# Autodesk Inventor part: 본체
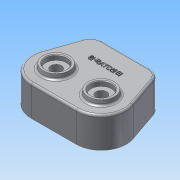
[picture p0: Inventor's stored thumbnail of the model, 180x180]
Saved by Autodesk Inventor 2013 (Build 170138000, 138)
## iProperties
Created: 2014-12
Part Number: 본체
Material: 알루미늄 6061
Document SubType Name: Modeling
Designer: Administrator
Density: 2.71 g/cm^3
Mass: 612.316 g
Surface Area: 666.735 cm^2
Volume: 225.947 cm^3
Author: Administrator
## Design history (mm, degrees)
sketch "스케치1"
  geometry: L1 (-47, 36)-(47, 36); L2 (47, 36)-(66.565, -20.803); L3 (32.527, -68.527)-(-32.527, -68.527); L4 (-66.565, -20.803)-(-47, 36); L5 (0, 0)-(-32.527, -32.527); L6 (0, 0)-(32.527, -32.527); A1 r 36 centre (-32.527, -32.527) between (-66.565, -20.803) and (-32.527, -68.527); A2 r 36 centre (32.527, -32.527) between (32.527, -68.527) and (66.565, -20.803); 2 further points
  constraints: 12 end point, 4 point on circle, 4 tangent, 2 centre point, 2 midpoint, 2 perpendicular, 2 vertical alignment, 1 horizontal, 1 parallel
  dimensions: "d0" = 94 distance of L1.start L1.end; "d89" = 72 diameter of A1; "d90" = 72 diameter of A2; "d91" = 36 distance from line of L1 L5.start; "d92" = 46 distance of L5.start L5.end
extrude "돌출1" new body sketch "스케치1" distance "d30" = 44; taper "d31" = 0 deg
fillet "모깎기2" dims "d33" = 18
sketch "스케치13"
  geometry: L1 (-34.162, 36)-(34.162, 36) reference; L2 (51.181, 23.862)-(66.565, -20.803) reference; L3 (-66.565, -20.803)-(-51.181, 23.862) reference; L4 (-34.162, 36)-(34.162, 36) reference; L5 (32.527, -68.527)-(-32.527, -68.527) reference; A1 r 18 centre (-34.162, 18) between (-34.162, 36) and (-51.181, 23.862) reference; A2 r 18 centre (34.162, 18) between (51.181, 23.862) and (34.162, 36) reference; A3 r 36 centre (32.527, -32.527) between (32.527, -68.527) and (66.565, -20.803) reference; A4 r 36 centre (-32.527, -32.527) between (-66.565, -20.803) and (-32.527, -68.527) reference; 2 further points
  constraints: 1 vertical alignment, 1 other
  dimensions: "d86" = 30 distance from line of L1 point (0, 6)
feature "엠보싱1" sketch "스케치13" dims "d0" = 94, "d87" = 1, "d88" = 0, "d89" = 72, "d90" = 72, "d91" = 36, "d92" = 46
sketch "스케치14"
  geometry: L1 (-51.181, 23.862)-(-66.565, -20.803) reference; L2 (-32.527, -68.527)-(32.527, -68.527) reference; L3 (66.565, -20.803)-(51.181, 23.862) reference; L4 (34.162, 36)-(-34.162, 36) reference; L5 (-46.453, 22.233)-(-61.837, -22.432); L6 (-32.527, -63.527)-(32.527, -63.527); L7 (61.837, -22.432)-(46.453, 22.233); L8 (34.162, 31)-(-34.162, 31); A1 r 18 centre (-34.162, 18) between (-34.162, 36) and (-51.181, 23.862) reference; A2 r 36 centre (-32.527, -32.527) between (-66.565, -20.803) and (-32.527, -68.527) reference; A3 r 36 centre (32.527, -32.527) between (32.527, -68.527) and (66.565, -20.803) reference; A4 r 18 centre (34.162, 18) between (51.181, 23.862) and (34.162, 36) reference; A5 r 13 centre (-34.162, 18) between (-34.162, 31) and (-46.453, 22.233); A6 r 31 centre (-32.527, -32.527) between (-61.837, -22.432) and (-32.527, -63.527); A7 r 31 centre (32.527, -32.527) between (32.527, -63.527) and (61.837, -22.432); A8 r 13 centre (34.162, 18) between (46.453, 22.233) and (34.162, 31); 1 further point
  constraints: 8 end point, 8 point on circle, 4 centre point, 7 other
  dimensions: "d93" = 5 distance between parallel lines of L4 L8
extrude "돌출8" cut sketch "스케치14" distance "d94" = 34; taper "d95" = 0 deg
sketch "스케치15"
  geometry: C1 r 24 at (0, 0); C2 r 24 at (-32.527, -32.527); C3 r 24 at (32.527, -32.527); A1 r 31 centre (-32.527, -32.527) between (-61.837, -22.432) and (-32.527, -63.527) reference; A2 r 31 centre (32.527, -32.527) between (32.527, -63.527) and (61.837, -22.432) reference; 1 further point
  constraints: 3 centre point, 3 coincident
  dimensions: "d96" = 48 diameter of C1; "d97" = 48 diameter of C2; "d98" = 48 diameter of C3
extrude "돌출9" join sketch "스케치15" distance "d99" = 11; taper "d100" = 0 deg
sketch "스케치16"
  geometry: C1 r 20 at (0, 0); A1 r 24 centre (0, 0) between (21.111, -11.416) and (-21.111, -11.416) reference
  constraints: 1 centre point, 1 coincident
  dimensions: "d101" = 40 diameter of C1
extrude "돌출10" cut sketch "스케치16" distance "d102" = 12; taper "d103" = 0 deg
sketch "스케치17"
  geometry: C1 r 20 at (0, 0) reference; C2 r 10 at (0, 0)
  constraints: 1 centre point, 1 coincident
  dimensions: "d104" = 20 diameter of C2
extrude "돌출11" cut sketch "스케치17" distance "d105" = 3; taper "d106" = 0 deg
sketch "스케치18"
  geometry: C1 r 20 at (0, 0) reference; C2 r 17.5 at (-32.527, -32.527); C3 r 17.5 at (32.527, -32.527); A1 r 24 centre (0, 0) between (-11.416, -21.111) and (11.416, -21.111) reference; A2 r 24 centre (32.527, -32.527) between (11.416, -21.111) and (21.111, -11.416) reference; A3 r 24 centre (0, 0) between (21.111, -11.416) and (-21.111, -11.416) reference; A4 r 24 centre (-32.527, -32.527) between (-21.111, -11.416) and (-11.416, -21.111) reference
  constraints: 2 centre point, 2 coincident
  dimensions: "d107" = 35 diameter of C2; "d108" = 35 diameter of C3
extrude "돌출12" cut sketch "스케치18" distance "d109" = 11; taper "d110" = 0 deg
sketch "스케치19"
  geometry: C1 r 20 at (-32.527, -32.527); C2 r 20 at (32.527, -32.527); A1 r 36 centre (-32.527, -32.527) between (-66.565, -20.803) and (-32.527, -68.527) reference; A2 r 36 centre (32.527, -32.527) between (32.527, -68.527) and (66.565, -20.803) reference; 1 further point
  constraints: 2 centre point, 2 coincident
  dimensions: "d111" = 40 diameter of C1; "d112" = 40 diameter of C2
extrude "돌출13" join sketch "스케치19" distance "d113" = 7; taper "d114" = -10 deg
sketch "스케치20"
  geometry: C1 r 18.766 at (0, 0) reference; C2 r 18.766 at (65.054, 0) reference; 3 further points
  constraints: 2 coincident
hole "구멍4" sketch "스케치20" at (0, 0), (65.054, 0) diameter "d115" = 15.5; stored, may be unused: countersink angle "d119" = 90 deg, drill point angle "d121" = 118 deg; dims "d116" = 20, "d117" = 30, "d118" = 7, "d120" = 23
sketch "스케치21"
  geometry: L1 (-61.837, -22.432)-(-46.453, 22.233) reference; L2 (46.453, 22.233)-(61.837, -22.432) reference; L3 (32.527, -63.527)-(-32.527, -63.527) reference; L4 (34.162, 36)-(-34.162, 36) reference; A1 r 8 centre (-51.7, 7) between (-54.305, -0.564) and (-49.095, 14.564); A2 r 8 centre (51.7, 7) between (49.095, 14.564) and (54.305, -0.564); A3 r 8 centre (0, -63.527) between (8, -63.527) and (-8, -63.527); 1 further point
  constraints: 8 point on line, 6 point on circle, 3 centre point, 1 horizontal alignment, 1 midpoint
  dimensions: "d122" = 16 diameter of A1; "d123" = 16 diameter of A2; "d124" = 29 distance from line of L4 A1.centre; "d125" = 16 diameter of A3
extrude "돌출14" join sketch "스케치21" stored distance "d126" = 7; taper "d127" = 0 deg
sketch "스케치22"
  geometry: A1 r 8 centre (-51.7, 7) between (-54.305, -0.564) and (-49.095, 14.564) reference; A2 r 8 centre (51.7, 7) between (49.095, 14.564) and (54.305, -0.564) reference; A3 r 8 centre (0, -63.527) between (8, -63.527) and (-8, -63.527) reference; 4 further points
  constraints: 3 coincident
hole "구멍5" sketch "스케치22" at (-51.7, 7), (51.7, 7), (0, -63.527) diameter "d128" = 4.134; stored, may be unused: countersink angle "d132" = 90 deg, drill point angle "d134" = 118 deg; dims "d129" = 20, "d130" = 30, "d131" = 7, "d133" = 23
fillet "모깎기3" dims "d135" = 3
fillet "모깎기4" dims "d136" = 3
fillet "모깎기5" dims "d137" = 0.1
chamfer "모따기1" distance "d138" = 1; stored, may be unused: second distance "d139" = 2, angle "d140" = 45 deg
fillet "모깎기6" dims "d141" = 0.3
node "솔리드1"
node "투영된 루프1"
node "투영된 루프2"
node "절단 모서리 투영4"
